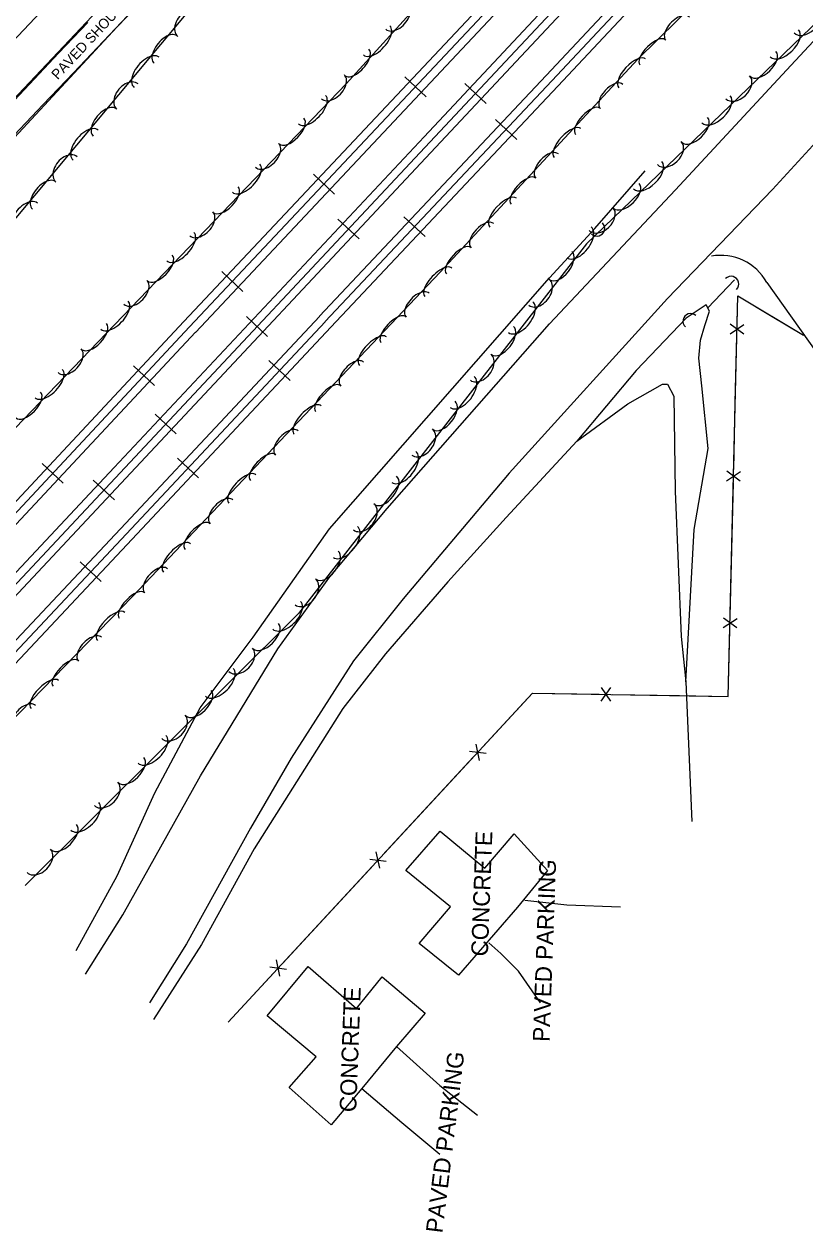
# Model space of a CAD drawing. Extents: x 978516 to 993312, y 1836504 to 1846212.
# Drawn here: x 991600.6 to 991834.3, y 1838346.2 to 1838707.8 of the extents above; entities that cross this region are included whole.
import ezdxf

# ---------------------------------------------------------------- set-up
doc = ezdxf.new("R2010")
doc.units = 0
for name, color, linetype in [('S_CROSS_DRAIN', 7, 'Continuous'), ('S_EDGE_PAVEMENT', 7, 'Continuous'), ('S_FENCE', 7, 'Continuous'), ('S_PARKING', 7, 'Continuous'), ('S_PARKING_ANNOT', 7, 'Continuous'), ('S_PAVEMENT_CROWN', 7, 'Continuous'), ('S_RAILROAD', 7, 'Continuous'), ('S_SHOULDER', 7, 'Continuous'), ('S_SHOULDER_ANNOT', 7, 'Continuous'), ('S_STREAM', 7, 'Continuous'), ('S_TREE', 7, 'Continuous')]:
    doc.layers.add(name, color=color, linetype=linetype)

msp = doc.modelspace()

# ---------------------------------------------------------------- linework, layer by layer
at = {"layer": 'S_CROSS_DRAIN'}
for centre, start, end in [((991772.07, 1838646.65), 225.5736, 45.9027), ((991812.21, 1838630), 315.0665, 135.3956), ((991800.09, 1838618.84), 47.5681, 227.8973)]:
    msp.add_arc(centre, 2.3, start, end, dxfattribs=at)
at = {"layer": 'S_EDGE_PAVEMENT'}
for points in [[(991746.04, 1838843.49), (991698.33, 1838792.55), (991662.41, 1838754.02), (991629.36, 1838719.16), (991598.85, 1838686.7), (991571.05, 1838657.4), (991537.37, 1838620.87), (991504.84, 1838586.6), (991475.64, 1838555.43)], [(991619, 1838423.36), (991630.2, 1838441.16), (991653.43, 1838482.79), (991676.53, 1838520.74), (991692.11, 1838542.33), (991709.31, 1838562.78), (991757.84, 1838618.11), (991795.59, 1838658.21), (991828.79, 1838694.04), (991858.22, 1838725.78)], [(991619.65, 1838708.32), (991610.91, 1838699.09), (991602.18, 1838689.87), (991591.41, 1838678.47), (991580.65, 1838667.07), (991569.89, 1838655.68), (991559.12, 1838644.28), (991549.63, 1838634.15), (991540.14, 1838624.01), (991530.64, 1838613.88), (991521.15, 1838603.74), (991507.4, 1838588.99), (991493.65, 1838574.24), (991479.9, 1838559.49), (991466.15, 1838544.73)], [(991871.79, 1838709.82), (991824.61, 1838658.29), (991793.15, 1838625.63), (991745.8, 1838573.38), (991714.08, 1838535.8), (991699.23, 1838517.15), (991680.52, 1838488.09), (991668.35, 1838467.09), (991649.18, 1838432.48), (991638.1, 1838414.83)]]:
    msp.add_lwpolyline(points, dxfattribs=at)
at = {"layer": 'S_FENCE'}
for p, q in [((991811.9, 1838615.11), (991816.06, 1838617.88)), ((991815.99, 1838615.01), (991811.97, 1838617.98)), ((991810.85, 1838571.12), (991815.02, 1838573.89)), ((991814.95, 1838571.02), (991810.92, 1838573.99)), ((991809.81, 1838527.13), (991813.97, 1838529.9)), ((991813.9, 1838527.03), (991809.88, 1838530)), ((991773.28, 1838505.11), (991776.21, 1838509.16)), ((991773.34, 1838509.21), (991776.15, 1838505.07)), ((991733.92, 1838490.17), (991738.87, 1838489.5)), ((991736.92, 1838487.39), (991735.86, 1838492.28)), ((991704.05, 1838457.86), (991709, 1838457.18)), ((991707.06, 1838455.08), (991705.99, 1838459.96)), ((991674.18, 1838425.54), (991679.13, 1838424.87)), ((991677.19, 1838422.76), (991676.13, 1838427.65))]:
    msp.add_line(p, q, dxfattribs=at)
for points in [[(991811.37, 1838506.52), (991814.22, 1838626.46), (991833.85, 1838614.66)], [(991814.03, 1838618.5), (991814.22, 1838626.46), (991824.54, 1838620.26)], [(991824.54, 1838620.26), (991833.85, 1838614.66)], [(991813.46, 1838594.5), (991813.93, 1838614.5)], [(991812.98, 1838574.5), (991813.46, 1838594.5)], [(991812.41, 1838550.51), (991812.89, 1838570.51)], [(991811.94, 1838530.51), (991812.41, 1838550.51)], [(991811.37, 1838506.52), (991811.84, 1838526.51)], [(991661.72, 1838409.05), (991752.75, 1838507.53)], [(991737.75, 1838491.3), (991751.33, 1838505.99)], [(991751.33, 1838505.99), (991752.75, 1838507.53)], [(991752.75, 1838507.49), (991772.75, 1838507.17)], [(991752.75, 1838507.49), (991811.37, 1838506.56)], [(991776.75, 1838507.11), (991796.75, 1838506.79)], [(991796.75, 1838506.79), (991811.37, 1838506.56)], [(991721.46, 1838473.68), (991735.04, 1838488.37)], [(991707.88, 1838458.99), (991721.46, 1838473.68)], [(991691.59, 1838441.36), (991705.17, 1838456.05)], [(991678.01, 1838426.68), (991691.59, 1838441.36)], [(991661.72, 1838409.05), (991675.3, 1838423.74)]]:
    msp.add_lwpolyline(points, dxfattribs=at)
at = {"layer": 'S_PARKING'}
for points in [[(991822.88, 1838630.45), (991840.3, 1838606), (991845.75, 1838595.15), (991863.14, 1838610.43), (991853.21, 1838624.61), (991862.11, 1838634.21), (991857.63, 1838646.95), (991851.24, 1838653.56), (991846.76, 1838655.98), (991842.93, 1838654.7), (991838.6, 1838651.92)], [(991718.86, 1838432.58), (991728.26, 1838443.52), (991714.88, 1838454.46), (991725.15, 1838466.17)], [(991725.15, 1838466.17), (991738.49, 1838455.14), (991747.28, 1838465.43), (991757.23, 1838454.37), (991748.25, 1838443.44), (991730.57, 1838423.13), (991718.86, 1838432.58)], [(991750.43, 1838445.55), (991763.06, 1838444.11), (991779.12, 1838443.53)], [(991755.11, 1838414.85), (991748.58, 1838424.28), (991743.24, 1838429.54), (991739.66, 1838432.72)], [(991720.66, 1838411.72), (991712.03, 1838401.73), (991701.66, 1838389.18), (991692.48, 1838378.31), (991679.93, 1838389.43), (991687.98, 1838398.65), (991673.34, 1838410.94), (991685.62, 1838425.65), (991700.06, 1838413.06)], [(991700.06, 1838413.06), (991707.8, 1838422.62), (991720.66, 1838411.72)], [(991712.03, 1838401.73), (991725.05, 1838390.06), (991736.34, 1838381.2)], [(991701.66, 1838389.18), (991713.62, 1838378.96), (991725.04, 1838369.46)]]:
    msp.add_lwpolyline(points, dxfattribs=at)
msp.add_ellipse((991809.14, 1838622.92), major_axis=(-11.26, 10.89), ratio=0.999798, start_param=4.411524, end_param=5.661309, dxfattribs=at)
at = {"layer": 'S_PAVEMENT_CROWN'}
msp.add_lwpolyline([(991610.75, 1838717.01), (991593.64, 1838698.83), (991582.34, 1838686.98), (991571.05, 1838675.12), (991559.75, 1838663.27), (991548.46, 1838651.42), (991539.41, 1838641.65), (991530.36, 1838631.89), (991521.31, 1838622.12), (991512.26, 1838612.35), (991498.5, 1838597.64), (991484.73, 1838582.94), (991470.97, 1838568.23), (991457.21, 1838553.52)], dxfattribs=at)
at = {"layer": 'S_RAILROAD'}
for p, q in [((991720.89, 1838686.06), (991714.57, 1838692)), ((991716.03, 1838690.63), (991716.11, 1838690.56)), ((991732.53, 1838689.99), (991738.87, 1838684.07)), ((991733.97, 1838688.65), (991733.99, 1838688.63)), ((991719.46, 1838687.41), (991719.44, 1838687.43)), ((991737.41, 1838685.43), (991737.33, 1838685.5)), ((991748.03, 1838673.31), (991741.72, 1838679.26)), ((991743.17, 1838677.89), (991743.25, 1838677.81)), ((991746.6, 1838674.66), (991746.58, 1838674.68)), ((991693.49, 1838656.92), (991687.17, 1838662.86)), ((991688.63, 1838661.49), (991688.7, 1838661.42)), ((991692.06, 1838658.26), (991692.03, 1838658.29)), ((991694.53, 1838649.43), (991700.86, 1838643.49)), ((991720.61, 1838644.18), (991714.3, 1838650.13)), ((991695.96, 1838648.08), (991695.99, 1838648.06)), ((991715.76, 1838648.76), (991715.83, 1838648.69)), ((991719.19, 1838645.53), (991719.16, 1838645.55)), ((991699.4, 1838644.86), (991699.32, 1838644.93)), ((991666.09, 1838627.77), (991659.77, 1838633.72)), ((991661.23, 1838632.35), (991661.3, 1838632.28)), ((991664.66, 1838629.12), (991664.63, 1838629.15)), ((991667.17, 1838620.23), (991673.5, 1838614.3)), ((991668.61, 1838618.89), (991668.63, 1838618.87)), ((991672.04, 1838615.67), (991671.97, 1838615.74)), ((991639.65, 1838599.61), (991633.32, 1838605.54)), ((991680.21, 1838601.16), (991673.88, 1838607.09)), ((991675.34, 1838605.72), (991675.41, 1838605.65)), ((991634.78, 1838604.17), (991634.85, 1838604.1)), ((991678.77, 1838602.5), (991678.75, 1838602.52)), ((991638.22, 1838600.95), (991638.19, 1838600.98)), ((991639.82, 1838591.04), (991646.15, 1838585.11)), ((991641.25, 1838589.7), (991641.28, 1838589.68)), ((991644.69, 1838586.48), (991644.61, 1838586.55)), ((991652.84, 1838571.97), (991646.52, 1838577.91)), ((991647.98, 1838576.54), (991648.05, 1838576.47)), ((991612.34, 1838570.39), (991606, 1838576.31)), ((991607.46, 1838574.94), (991607.54, 1838574.87)), ((991651.41, 1838573.32), (991651.38, 1838573.34)), ((991610.91, 1838571.73), (991610.88, 1838571.75)), ((991621.31, 1838571.29), (991627.64, 1838565.36)), ((991622.74, 1838569.95), (991622.77, 1838569.92)), ((991626.18, 1838566.73), (991626.11, 1838566.8)), ((991623.68, 1838540.89), (991617.35, 1838546.83)), ((991618.81, 1838545.46), (991618.89, 1838545.39)), ((991622.25, 1838542.24), (991622.22, 1838542.26))]:
    msp.add_line(p, q, dxfattribs=at)
for points in [[(991805.41, 1838785.8), (991729.73, 1838705.21)], [(991807.11, 1838784.2), (991731.44, 1838703.61)], [(991808.84, 1838782.58), (991733.17, 1838701.98)], [(991720.3, 1838674.05), (991815.31, 1838775.52)], [(991722.03, 1838672.43), (991817.04, 1838773.9)], [(991723.73, 1838670.83), (991818.75, 1838772.3)], [(991825.1, 1838765.3), (991756.88, 1838692.45)], [(991826.8, 1838763.7), (991758.59, 1838690.85)], [(991828.54, 1838762.08), (991760.32, 1838689.23)], [(991729.73, 1838705.21), (991648.44, 1838618.75)], [(991731.44, 1838703.61), (991650.14, 1838617.15)], [(991733.16, 1838701.98), (991651.87, 1838615.52)], [(991756.88, 1838692.45), (991689.02, 1838620.36)], [(991758.59, 1838690.85), (991690.72, 1838618.76)], [(991760.31, 1838689.22), (991692.45, 1838617.13)], [(991717.75, 1838689.05), (991717.73, 1838689.03)], [(991735.68, 1838687.01), (991735.7, 1838687.03)], [(991744.9, 1838676.3), (991744.88, 1838676.28)], [(991627.58, 1838575.11), (991720.3, 1838674.05)], [(991629.31, 1838573.48), (991722.03, 1838672.43)], [(991631.01, 1838571.89), (991723.73, 1838670.83)], [(991690.35, 1838659.91), (991690.33, 1838659.89)], [(991697.67, 1838646.44), (991697.69, 1838646.46)], [(991717.48, 1838647.18), (991717.46, 1838647.16)], [(991662.95, 1838630.77), (991662.93, 1838630.75)], [(991689.02, 1838620.31), (991632.51, 1838560.04)], [(991648.43, 1838618.78), (991559.4, 1838523.51)], [(991650.14, 1838617.19), (991561.11, 1838521.91)], [(991690.72, 1838618.71), (991634.21, 1838558.44)], [(991692.45, 1838617.09), (991635.94, 1838556.82)], [(991670.32, 1838617.25), (991670.34, 1838617.27)], [(991651.88, 1838615.57), (991562.84, 1838520.29)], [(991636.51, 1838602.59), (991636.49, 1838602.57)], [(991677.06, 1838604.14), (991677.04, 1838604.12)], [(991642.96, 1838588.06), (991642.98, 1838588.08)], [(991554.37, 1838496.96), (991627.58, 1838575.11)], [(991556.1, 1838495.34), (991629.31, 1838573.48)], [(991609.19, 1838573.37), (991609.17, 1838573.35)], [(991649.7, 1838574.96), (991649.68, 1838574.94)], [(991557.81, 1838493.74), (991631.01, 1838571.89)], [(991624.46, 1838568.31), (991624.48, 1838568.33)], [(991632.51, 1838560.04), (991565.46, 1838488.67)], [(991634.21, 1838558.44), (991567.16, 1838487.07)], [(991635.94, 1838556.81), (991568.89, 1838485.45)], [(991620.54, 1838543.88), (991620.52, 1838543.86)]]:
    msp.add_lwpolyline(points, dxfattribs=at)
at = {"layer": 'S_SHOULDER'}
for points in [[(991481.77, 1838550.64), (991512.49, 1838583.3), (991540.49, 1838613.66), (991564.31, 1838638.85), (991595.13, 1838671.09), (991628.38, 1838706.87), (991645.99, 1838725.21), (991676.99, 1838757.95), (991700.31, 1838783.09), (991721.71, 1838805.72), (991743.86, 1838829.58), (991749.45, 1838835.42)], [(991633.39, 1838712.2), (991624.37, 1838702.72), (991615.35, 1838693.25), (991606.33, 1838683.77), (991595.93, 1838672.76), (991585.53, 1838661.75), (991575.13, 1838650.73), (991564.73, 1838639.72), (991554.98, 1838629.41), (991545.22, 1838619.1), (991535.47, 1838608.78), (991525.71, 1838598.47), (991509.28, 1838580.74), (991492.84, 1838563.01), (991482.02, 1838551.34), (991471.19, 1838539.67)]]:
    msp.add_lwpolyline(points, dxfattribs=at)
at = {"layer": 'S_STREAM'}
for points in [[(991616.23, 1838430.42), (991628.46, 1838452.81), (991639.74, 1838477.68), (991653.28, 1838503.08), (991669.18, 1838524.3), (991691.98, 1838556.7), (991757.88, 1838631.81), (991771.42, 1838646.65), (991786.53, 1838663.91)], [(991805.26, 1838622.83), (991813.26, 1838631.21)], [(991804.76, 1838623.79), (991798.79, 1838619.79), (991783.79, 1838604.1), (991766.01, 1838582.93), (991781.3, 1838594.1), (991791.65, 1838600)], [(991791.65, 1838600), (991793.19, 1838599.97), (991795.09, 1838596.43), (991795.48, 1838567.95), (991797.29, 1838524.49), (991798.69, 1838510.86), (991801.17, 1838556.46), (991805.35, 1838580.8), (991803.46, 1838599.55), (991802.5, 1838607.83), (991803.08, 1838613.2), (991804.33, 1838617.63), (991805.76, 1838621.88), (991804.76, 1838623.79)], [(991766.01, 1838582.93), (991744.91, 1838560.07), (991727.4, 1838540.8), (991708.79, 1838519.31), (991696.03, 1838502.92), (991669.43, 1838460.91), (991653.67, 1838432.3), (991639.36, 1838409.78)], [(991798.69, 1838510.86), (991800.4, 1838469.05)]]:
    msp.add_lwpolyline(points, dxfattribs=at)
at = {"layer": 'S_TREE'}
for points in [[(991493.26, 1838536.17), (991578.55, 1838626.35), (991654.1, 1838716.88), (991713.11, 1838774.16), (991744.99, 1838784.07), (991815.81, 1838859.94), (991816.53, 1838886.99), (991861.97, 1838935.67), (991889.69, 1838945.79), (991911.91, 1838973.15)], [(991929.76, 1838941.43), (991813.48, 1838818.13), (991696.96, 1838689.98), (991583.05, 1838571.46), (991519.67, 1838503.08)], [(991575.9, 1838477.68), (991633.08, 1838536.44), (991725.15, 1838633.51), (991784.28, 1838697.34), (991843.59, 1838755.72)], [(991860.31, 1838730.14), (991768.97, 1838641.99), (991682.77, 1838531.4), (991600.96, 1838449.93)]]:
    msp.add_lwpolyline(points, dxfattribs=at)
for centre, major_axis, ratio, start_param, end_param in [((991649.74, 1838707.94), (-3.17, -3.8), 0.685397, 3.141172, 6.282765), ((991712.17, 1838709.94), (3.34, 3.66), 0.624841, 3.146429, 6.288022), ((991796.18, 1838706.43), (-3.5, -3.5), 0.537648, 3.126843, 6.268436), ((991834.64, 1838708.66), (3.57, 3.44), 0.682618, 3.141593, 6.283185), ((991706.12, 1838702.93), (3.95, 4.34), 0.501546, 3.144754, 6.286347), ((991642.94, 1838700.19), (-3.42, -4.1), 0.540767, 3.141344, 6.282937), ((991788.7, 1838699.35), (-3.79, -3.77), 0.424226, 3.131504, 6.273096), ((991828.16, 1838702.05), (4.22, 4.08), 0.547918, 3.141593, 6.283185), ((991700.16, 1838696.37), (3.6, 3.95), 0.492993, 3.144665, 6.286258), ((991821.77, 1838695.89), (3.85, 3.71), 0.538574, 3.141593, 6.283185), ((991637.26, 1838693.39), (-3.76, -4.51), 0.550149, 3.141336, 6.282929), ((991782.6, 1838693.07), (-3.99, -4.31), 0.431378, 3.141593, 6.283185), ((991693.03, 1838689.02), (3.43, 3.57), 0.624754, 3.141522, 6.283115), ((991814.18, 1838688.92), (3.57, 3.44), 0.682618, 3.141593, 6.283185), ((991631.53, 1838686.11), (-3.17, -3.8), 0.685397, 3.141172, 6.282765), ((991776.46, 1838686.14), (-3.37, -3.64), 0.537427, 3.141593, 6.283185), ((991686.78, 1838682.18), (4.07, 4.23), 0.501473, 3.141546, 6.283139), ((991807.7, 1838682.3), (4.22, 4.08), 0.547918, 3.141593, 6.283185), ((991624.73, 1838678.37), (-3.42, -4.1), 0.540767, 3.141344, 6.282937), ((991769.3, 1838678.72), (-3.63, -3.92), 0.424021, 3.141593, 6.283185), ((991680.64, 1838675.78), (3.7, 3.85), 0.492921, 3.141548, 6.28314), ((991801.32, 1838676.14), (3.85, 3.71), 0.538574, 3.141593, 6.283185), ((991619.05, 1838671.56), (-3.76, -4.51), 0.550149, 3.141336, 6.282929), ((991763.28, 1838672.22), (-3.99, -4.31), 0.431378, 3.141593, 6.283185), ((991673.32, 1838668.52), (3.43, 3.57), 0.624754, 3.141522, 6.283115), ((991793.72, 1838669.18), (3.57, 3.44), 0.682618, 3.141593, 6.283185), ((991613.31, 1838664.29), (-3.17, -3.8), 0.685397, 3.141172, 6.282765), ((991757.13, 1838665.29), (-3.37, -3.64), 0.537427, 3.141593, 6.283185), ((991667.08, 1838661.68), (4.07, 4.23), 0.501473, 3.141546, 6.283139), ((991787.24, 1838662.56), (4.22, 4.08), 0.547918, 3.141593, 6.283185), ((991606.51, 1838656.55), (-3.42, -4.1), 0.540767, 3.141344, 6.282937), ((991749.98, 1838657.87), (-3.63, -3.92), 0.424021, 3.141593, 6.283185), ((991780.86, 1838656.4), (3.85, 3.71), 0.538574, 3.141593, 6.283185), ((991660.94, 1838655.29), (3.7, 3.85), 0.492921, 3.141548, 6.28314), ((991743.96, 1838651.36), (-3.99, -4.31), 0.431378, 3.141593, 6.283185), ((991600.83, 1838649.74), (-3.76, -4.51), 0.550149, 3.141336, 6.282929), ((991773.26, 1838649.43), (3.57, 3.44), 0.682618, 3.141593, 6.283185), ((991653.62, 1838648.02), (3.43, 3.57), 0.624754, 3.141522, 6.283115), ((991737.81, 1838644.43), (-3.37, -3.64), 0.537427, 3.141593, 6.283185), ((991647.38, 1838641.18), (4.07, 4.23), 0.501473, 3.141546, 6.283139), ((991766.69, 1838642.5), (3.61, 4.63), 0.547964, 3.14184, 6.283433), ((991730.66, 1838637.01), (-3.63, -3.92), 0.424021, 3.141593, 6.283185), ((991641.23, 1838634.79), (3.7, 3.85), 0.492921, 3.141548, 6.28314), ((991761.24, 1838635.51), (3.29, 4.22), 0.53862, 3.141833, 6.283425), ((991724.6, 1838630.52), (-4.04, -4.25), 0.431366, 3.144356, 6.285949), ((991633.92, 1838627.53), (3.43, 3.57), 0.624754, 3.141522, 6.283115), ((991754.7, 1838627.54), (3.05, 3.91), 0.682675, 3.141997, 6.28359), ((991718.38, 1838623.66), (-3.42, -3.59), 0.53741, 3.145533, 6.287126), ((991627.68, 1838620.68), (4.07, 4.23), 0.501473, 3.141546, 6.283139), ((991749.21, 1838620.08), (3.61, 4.63), 0.547964, 3.14184, 6.283433), ((991711.14, 1838616.32), (-3.68, -3.87), 0.42401, 3.144288, 6.285881), ((991621.53, 1838614.29), (3.7, 3.85), 0.492921, 3.141548, 6.28314), ((991743.76, 1838613.08), (3.29, 4.22), 0.53862, 3.141833, 6.283425), ((991705.04, 1838609.89), (-4.04, -4.25), 0.431366, 3.144356, 6.285949), ((991614.22, 1838607.03), (3.43, 3.57), 0.624754, 3.141522, 6.283115), ((991698.82, 1838603.03), (-3.42, -3.59), 0.53741, 3.145533, 6.287126), ((991737.22, 1838605.11), (3.05, 3.91), 0.682675, 3.141997, 6.28359), ((991607.98, 1838600.19), (4.07, 4.23), 0.501473, 3.141546, 6.283139), ((991731.73, 1838597.65), (3.61, 4.63), 0.547964, 3.14184, 6.283433), ((991691.58, 1838595.7), (-3.68, -3.87), 0.42401, 3.144288, 6.285881), ((991601.83, 1838593.79), (3.7, 3.85), 0.492921, 3.141548, 6.28314), ((991726.28, 1838590.66), (3.29, 4.22), 0.53862, 3.141833, 6.283425), ((991685.47, 1838589.26), (-4.04, -4.25), 0.431366, 3.144356, 6.285949), ((991679.25, 1838582.4), (-3.42, -3.59), 0.53741, 3.145533, 6.287126), ((991719.74, 1838582.69), (3.05, 3.91), 0.682675, 3.141997, 6.28359), ((991672.01, 1838575.07), (-3.68, -3.87), 0.42401, 3.144288, 6.285881), ((991714.26, 1838575.23), (3.61, 4.63), 0.547964, 3.14184, 6.283433), ((991665.91, 1838568.64), (-4.04, -4.25), 0.431366, 3.144356, 6.285949), ((991708.81, 1838568.23), (3.29, 4.22), 0.53862, 3.141833, 6.283425), ((991659.69, 1838561.78), (-3.42, -3.59), 0.53741, 3.145533, 6.287126), ((991702.27, 1838560.27), (3.05, 3.91), 0.682675, 3.141997, 6.28359), ((991652.45, 1838554.44), (-3.68, -3.87), 0.42401, 3.144288, 6.285881), ((991696.78, 1838552.8), (3.61, 4.63), 0.547964, 3.14184, 6.283433), ((991646.34, 1838548.01), (-4.04, -4.25), 0.431366, 3.144356, 6.285949), ((991691.33, 1838545.81), (3.29, 4.22), 0.53862, 3.141833, 6.283425), ((991640.12, 1838541.15), (-3.42, -3.59), 0.53741, 3.145533, 6.287126), ((991684.79, 1838537.84), (3.05, 3.91), 0.682675, 3.141997, 6.28359), ((991632.84, 1838533.81), (-3.73, -3.83), 0.424013, 3.140839, 6.282431), ((991679.2, 1838530.82), (4.16, 4.14), 0.547959, 3.142443, 6.284036), ((991626.66, 1838527.45), (-4.09, -4.21), 0.431369, 3.14082, 6.282412), ((991672.92, 1838524.56), (3.79, 3.77), 0.538615, 3.142417, 6.284009), ((991620.35, 1838520.68), (-3.45, -3.55), 0.537417, 3.14049, 6.282083), ((991665.43, 1838517.48), (3.51, 3.49), 0.682668, 3.142981, 6.284574), ((991613.01, 1838513.43), (-3.73, -3.83), 0.424013, 3.140839, 6.282431), ((991606.83, 1838507.08), (-4.09, -4.21), 0.431369, 3.14082, 6.282412), ((991659.06, 1838510.76), (4.16, 4.14), 0.547959, 3.142443, 6.284036), ((991652.77, 1838504.5), (3.79, 3.77), 0.538615, 3.142417, 6.284009), ((991600.52, 1838500.3), (-3.45, -3.55), 0.537417, 3.14049, 6.282083), ((991645.29, 1838497.42), (3.51, 3.49), 0.682668, 3.142981, 6.284574), ((991638.91, 1838490.7), (4.16, 4.14), 0.547959, 3.142443, 6.284036), ((991632.63, 1838484.44), (3.79, 3.77), 0.538615, 3.142417, 6.284009), ((991625.14, 1838477.36), (3.51, 3.49), 0.682668, 3.142981, 6.284574), ((991618.77, 1838470.64), (4.16, 4.14), 0.547959, 3.142443, 6.284036), ((991612.48, 1838464.39), (3.79, 3.77), 0.538615, 3.142417, 6.284009), ((991605, 1838457.3), (3.51, 3.49), 0.682668, 3.142981, 6.284574)]:
    msp.add_ellipse(centre, major_axis=major_axis, ratio=ratio, start_param=start_param, end_param=end_param, dxfattribs=at)

# ---------------------------------------------------------------- texts
at = {"layer": 'S_PARKING_ANNOT'}
for s, height, rotation, p in [('CONCRETE', 5, 87.88, (991739.38, 1838428.64)), ('PAVED PARKING', 5.0005, 87.88, (991757.84, 1838403.07)), ('CONCRETE', 5, 87.88, (991699.99, 1838382)), ('PAVED PARKING', 5.0005, 83.0466, (991725.79, 1838345.7))]:
    msp.add_text(s, height=height, rotation=rotation, dxfattribs=at).set_placement(p)
at = {"layer": 'S_SHOULDER_ANNOT'}
msp.add_text('PAVED SHOULDER', height=3.0003, rotation=46.9226, dxfattribs=at).set_placement((991610.66, 1838691))

doc.saveas('drawing.dxf')
